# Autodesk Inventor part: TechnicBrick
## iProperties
Shininess: 20.0
Length Units: 11269
Angle Units: 11279
Time Units: 11290
Mass Units: 11283
Length Display Precision: 3
Angle Display Precision: 2
Created: 2002-08
Part Number: TechnicBrick
Material: ABS Plastic
Document SubType Name: Modellieren
Designer: MP
Description: Brick 1x4 with Holes (3701) white
Catalog Web Link: www.iBricks.de
Vendor: The LEGO Group
Density: 0.0
Volumn: 0.0
Area: 0.0
PropertySet Name: Model Information
Control State: 0
Master: False
Checked Out: False
Author: Michael Puschner
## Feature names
1. Body [Extrusion]
2. Shell
3. Stud [Extrusion]
4. StudFillet [Fillet]
5. Studs [Rectangular Pattern]
6. SmallStud [Extrusion]
7. SmallStuds [Rectangular Pattern]
8. HoleRib [Extrusion]
9. AxelHole [Extrusion]
10. Hole [Extrusion]
11. SinkL [Extrusion]
12. SinkR [Extrusion]
13. Holes [Rectangular Pattern]
14. BodyFillet [Fillet]
